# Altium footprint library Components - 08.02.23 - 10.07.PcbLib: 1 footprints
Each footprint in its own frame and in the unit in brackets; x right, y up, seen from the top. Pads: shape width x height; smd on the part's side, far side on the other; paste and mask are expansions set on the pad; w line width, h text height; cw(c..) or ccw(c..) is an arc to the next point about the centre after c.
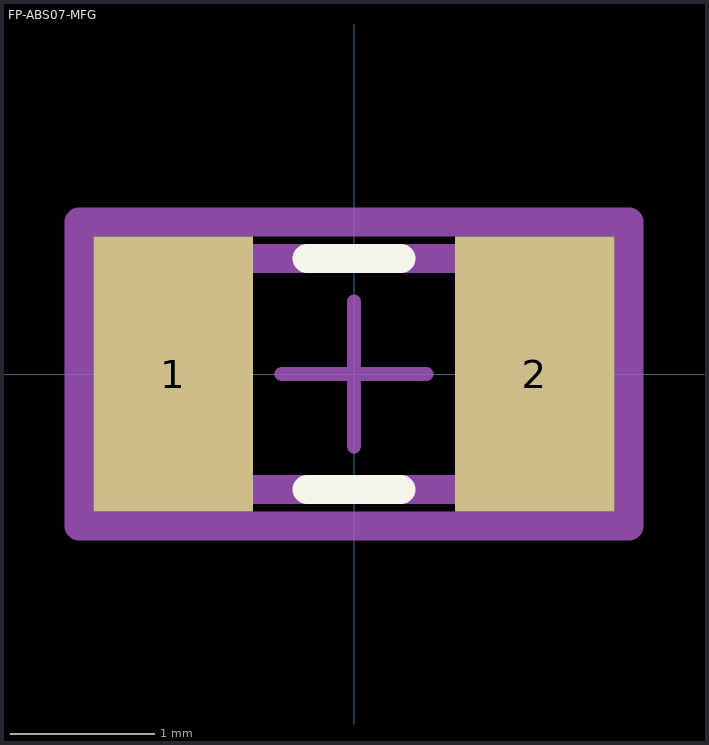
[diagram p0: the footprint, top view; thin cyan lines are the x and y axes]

## FP-ABS07-MFG [mm]
pads (2):
  rect 1.1x1.9 smd paste+0 mask+0: 1(-1.25,0) 2(1.25,0)
Top Overlay:
  lines w0.2: -0.325,-0.8 0.325,-0.8 ; -0.325,0.8 0.325,0.8
Top Assembly:
  lines w0.2: -1.9,-1.05 -1.9,1.05 1.9,1.05 1.9,-1.05 -1.9,-1.05
  text ".Designator" at 0,0.188 h1
Top 3D Body:
  lines w0.2: -1.65,-0.8 -1.65,0.8 1.65,0.8 1.65,-0.8 -1.65,-0.8
Top Courtyard:
  lines w0.2: -1.9,-1.05 -1.9,1.05 1.9,1.05 1.9,-1.05 -1.9,-1.05
Top Component Center:
  lines w0.1: -0.5,0 0.5,0 ; 0,-0.5 0,0.5
3D body "Crys_Abracon_ABS07-166-32_768KHZ-T_eec.STEP": height 0.25, standoff 0, extent -1.9,-1.05 1.9,1.05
